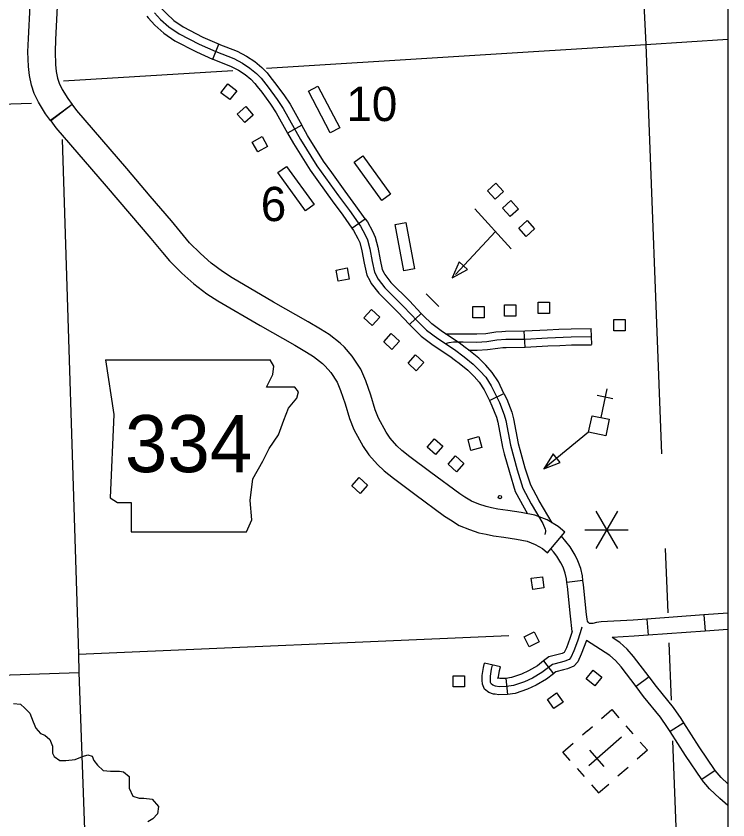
# Model space of a CAD drawing. Extents: x 155 to 3386, y 68 to 2138.
# Drawn here: x 2154 to 2342.2, y 715.4 to 927.8 of the extents above; entities that cross this region are included whole.
import ezdxf

# ---------------------------------------------------------------- set-up
doc = ezdxf.new("R2010")
doc.units = 0
for name, color, linetype in [('Default', 7, 'Continuous'), ('E_No Plot', 7, 'Continuous'), ('Level 10', 7, 'Continuous'), ('Level 21', 7, 'Continuous'), ('Level 31', 7, 'Continuous'), ('Level 32', 7, 'Continuous'), ('Level 35', 7, 'Continuous'), ('Level 4', 7, 'Continuous'), ('Level 48', 7, 'Continuous'), ('Level 5', 7, 'Continuous'), ('Level 56', 7, 'Continuous'), ('Level 57', 7, 'Continuous')]:
    doc.layers.add(name, color=color, linetype=linetype)

msp = doc.modelspace()

# ---------------------------------------------------------------- linework, layer by layer
at = {"layer": 'Default'}
msp.add_lwpolyline([(1150.5, 1308.99), (2342.15, 1308.99), (2342.15, 348.58), (1150.5, 348.58)], close=True, dxfattribs=at)
at = {"layer": 'E_No Plot'}
msp.add_lwpolyline([(1150.5, 1308.99), (2342.15, 1308.99), (2342.15, 348.58), (1150.5, 348.58)], close=True, dxfattribs=at)
msp.add_lwpolyline([(1150.5, 1308.99), (2342.15, 1308.99), (2342.15, 348.58), (1150.5, 348.58)], close=True, dxfattribs=at)
at = {"layer": 'Level 10'}
for p, q in [((2168.87, 904.47), (2163.16, 900.19)), ((2294.44, 786.01), (2299.05, 791.47))]:
    msp.add_line(p, q, dxfattribs=at)
for points in [[(2163.16, 900.19), (2161.77, 902.03), (2159.95, 905.04), (2158.8, 907.4), (2158.08, 909.54), (2157.58, 912.08), (2157.3, 914.48), (2157.17, 918.35), (2157.3, 921.92), (2157.78, 930.57)], [(2164.92, 930.33), (2164.43, 921.6), (2164.32, 918.34), (2164.43, 915.01), (2164.64, 913.18), (2164.99, 911.39), (2165.42, 910.12), (2166.23, 908.46), (2167.7, 906.04), (2168.87, 904.47)], [(2168.87, 904.47), (2163.19, 900.15), (2163.16, 900.19)], [(2299.05, 791.47), (2297.26, 792.98), (2294.35, 794.67), (2291.12, 795.96), (2287.48, 796.68), (2283.98, 797.18), (2281.36, 797.57), (2279.63, 797.88), (2278.24, 798.19), (2276.35, 798.83), (2274.38, 799.61), (2272.66, 800.71), (2271.3, 801.58), (2263.63, 807.24), (2258.11, 811.35), (2256, 813.03), (2254.69, 814.29), (2252.9, 816.29), (2251.85, 817.85), (2249.8, 821.57), (2248.95, 823.81), (2247.78, 827.61), (2246.47, 831.45), (2245.17, 834.48), (2242.88, 837.99), (2240.81, 840.36), (2239.64, 841.42), (2236.77, 843.71), (2234.52, 845.13), (2231.24, 847.06), (2222.07, 852.22), (2211.14, 858.62), (2208.55, 860.3), (2205.57, 862.57), (2202.75, 865.07), (2199.86, 867.94), (2198.29, 869.88), (2195.12, 873.7), (2189.47, 880.27), (2183.29, 887.55), (2170.12, 902.85), (2168.84, 904.51)], [(2163.19, 900.15), (2164.58, 898.33), (2177.86, 882.91), (2184.04, 875.63), (2189.66, 869.09), (2192.77, 865.35), (2194.55, 863.15), (2197.87, 859.86), (2201.02, 857.06), (2204.44, 854.46), (2207.39, 852.54), (2218.51, 846.02), (2227.68, 840.87), (2230.8, 839.03), (2232.63, 837.88), (2235, 835.98), (2235.72, 835.33), (2237.18, 833.67), (2238.85, 831.09), (2239.8, 828.88), (2240.99, 825.4), (2242.19, 821.5), (2243.3, 818.57), (2245.75, 814.12), (2247.26, 811.89), (2249.55, 809.33), (2251.29, 807.66), (2253.75, 805.69), (2259.38, 801.5), (2267.24, 795.7), (2268.8, 794.69), (2271.11, 793.23), (2273.89, 792.12), (2276.32, 791.3), (2278.22, 790.88), (2280.21, 790.52), (2282.95, 790.11), (2286.28, 789.64), (2289.09, 789.08), (2291.22, 788.23), (2293.13, 787.12), (2294.44, 786.01)]]:
    msp.add_lwpolyline(points, dxfattribs=at)
at = {"layer": 'Level 21'}
for p, q in [((2177.67, 837), (2179.85, 822.5)), ((2222.14, 835.3), (2221.14, 836.97)), ((2221.9, 833.13), (2222.14, 835.3)), ((2220.21, 829.75), (2221.9, 833.13)), ((2227.7, 829.75), (2220.21, 829.75)), ((2228.67, 828.54), (2227.7, 829.75)), ((2228.19, 826.85), (2228.67, 828.54)), ((2226.01, 824.19), (2228.19, 826.85)), ((2224.8, 821.04), (2226.01, 824.19)), ((2179.85, 822.5), (2178.88, 800.5)), ((2223.35, 817.18), (2224.8, 821.04)), ((2220.94, 813.55), (2223.35, 817.18)), ((2219.24, 810.17), (2220.94, 813.55)), ((2216.59, 805.58), (2219.24, 810.17)), ((2215.86, 799.78), (2216.59, 805.58)), ((2178.88, 800.5), (2180.82, 799.29)), ((2180.82, 799.29), (2184.44, 799.29)), ((2184.44, 799.29), (2184.44, 791.56)), ((2216.34, 794.7), (2215.86, 799.78)), ((2214.89, 791.56), (2216.34, 794.7)), ((2184.44, 791.56), (2214.89, 791.56))]:
    msp.add_line(p, q, dxfattribs=at)
msp.add_lwpolyline([(2177.67, 837), (2221.14, 836.97)], dxfattribs=at)
at = {"layer": 'Level 31'}
for p, q in [((2206.03, 916.43), (2207.59, 920.42)), ((2229.51, 899.01), (2225.77, 896.92)), ((2229.51, 899.01), (2229.51, 899.01)), ((2242.8, 871.77), (2246.29, 874.25)), ((2261.11, 849.24), (2257.99, 846.31)), ((2261.11, 849.24), (2261.11, 849.24)), ((2279.11, 826.25), (2282.96, 828.13))]:
    msp.add_line(p, q, dxfattribs=at)
for points in [[(2207.59, 920.42), (2212.42, 918.54), (2214.93, 917.26), (2217.1, 915.83), (2219, 914.26), (2220.4, 912.79), (2221.1, 911.9)], [(2206.81, 918.43), (2211.54, 916.58), (2213.85, 915.41), (2215.83, 914.1), (2217.54, 912.69), (2218.78, 911.39), (2220.65, 909.01), (2223.07, 905.75), (2224.61, 903.41), (2229.18, 895.22), (2233.53, 888.28), (2239.26, 880.3), (2242.11, 876.44), (2245.06, 872.29), (2246.29, 870.01), (2246.9, 868.7), (2247.5, 866.28), (2248.12, 862.93), (2248.79, 860.12), (2249.69, 858.34), (2251.5, 856.03), (2256.46, 851.07), (2260.11, 847.18), (2262.52, 844.85), (2265.5, 842.64), (2269.86, 839.72), (2272.41, 837.81), (2274.86, 835.82), (2276.63, 834.08), (2278.14, 832.37), (2279.61, 830.09), (2281.76, 825.7), (2283.03, 822.48), (2283.43, 820.96), (2284.67, 814.42), (2286.45, 807.89), (2287.96, 803.08), (2290.2, 798.93), (2293.22, 793.76), (2293.89, 792.26), (2293.93, 791.9), (2293.92, 791.63), (2293.79, 790.87)], [(2206.03, 916.43), (2210.66, 914.62), (2212.77, 913.55), (2214.55, 912.38), (2216.07, 911.12), (2217.15, 909.98), (2217.73, 909.25)], [(2221.1, 911.9), (2222.36, 910.31), (2224.82, 906.98), (2226.44, 904.52), (2229.51, 899.01)], [(2217.73, 909.25), (2218.95, 907.7), (2221.31, 904.53), (2222.77, 902.3), (2225.77, 896.92)], [(2237.46, 886.49), (2235.31, 889.48), (2231.02, 896.31), (2229.51, 899.01)], [(2225.77, 896.92), (2227.33, 894.13), (2231.75, 887.09), (2233.97, 883.99)], [(2246.29, 874.25), (2243.84, 877.7), (2240.99, 881.56), (2237.46, 886.49)], [(2233.97, 883.99), (2237.53, 879.04), (2240.37, 875.19), (2242.8, 871.77)], [(2246.29, 874.25), (2246.88, 873.42), (2248.21, 870.97), (2248.93, 869.41), (2249.6, 866.73), (2250.21, 863.37), (2250.81, 860.86), (2251.32, 859.86)], [(2242.8, 871.77), (2243.23, 871.15), (2244.38, 869.05), (2244.87, 867.99), (2245.4, 865.82), (2246.02, 862.49), (2246.76, 859.37), (2247.5, 857.92)], [(2251.32, 859.86), (2251.51, 859.5), (2253.11, 857.45), (2258, 852.56), (2261.11, 849.24)], [(2247.5, 857.92), (2247.88, 857.18), (2249.89, 854.6), (2254.92, 849.58), (2257.99, 846.31)], [(2272.72, 840.26), (2271.1, 841.47), (2266.74, 844.39), (2263.91, 846.49), (2261.64, 848.68), (2261.11, 849.24)], [(2257.99, 846.31), (2258.58, 845.67), (2261.13, 843.21), (2264.27, 840.89), (2268.62, 837.98), (2270.14, 836.83)], [(2282.96, 828.13), (2281.48, 831.15), (2279.85, 833.67), (2278.19, 835.56), (2276.29, 837.42), (2273.72, 839.5), (2272.72, 840.26)], [(2270.14, 836.83), (2271.09, 836.12), (2273.43, 834.22), (2275.08, 832.6), (2276.43, 831.07), (2277.75, 829.04), (2279.11, 826.25)], [(2282.96, 828.13), (2283.72, 826.57), (2285.07, 823.15), (2285.52, 821.43), (2286.76, 814.91), (2287.2, 813.31)], [(2279.11, 826.25), (2279.8, 824.83), (2280.99, 821.81), (2281.34, 820.49), (2282.58, 813.94), (2283.06, 812.18)], [(2283.06, 812.18), (2284.39, 807.29), (2285.97, 802.24), (2288.33, 797.88), (2289.23, 796.33)], [(2287.2, 813.31), (2288.51, 808.49), (2289.94, 803.92), (2292.07, 799.98), (2292.2, 799.76)], [(2292.2, 799.76), (2295.59, 793.95)]]:
    msp.add_lwpolyline(points, dxfattribs=at)
at = {"layer": 'Level 32'}
for p, q in [((2288.61, 840.32), (2288.3, 844.6)), ((2306.23, 841), (2306.04, 845.28)), ((2303.85, 778.71), (2299.6, 778.18)), ((2335.8, 769.57), (2336.11, 765.3)), ((2320.76, 768.49), (2321.07, 764.21)), ((2293.41, 757.42), (2296.05, 754.04)), ((2283.46, 752.82), (2283.86, 748.55)), ((2321.32, 753.22), (2317.91, 750.63)), ((2330.52, 741.07), (2326.91, 738.75)), ((2338.77, 728.5), (2335.22, 726.1))]:
    msp.add_line(p, q, dxfattribs=at)
for points in [[(2190.62, 928.7), (2192.23, 926.95), (2194.39, 924.98), (2197.12, 923.14), (2202.46, 920.36), (2206.81, 918.43)], [(2192.18, 930.22), (2192.31, 930.03), (2193.75, 928.47), (2195.72, 926.67), (2198.22, 924.98), (2203.39, 922.29), (2203.41, 922.28)], [(2188.63, 927.83), (2188.93, 927.37), (2190.72, 925.43), (2193.06, 923.29), (2196.03, 921.29), (2201.53, 918.43), (2201.67, 918.36)], [(2203.4, 922.28), (2207.68, 920.39)], [(2201.67, 918.36), (2205.94, 916.47)], [(2267.51, 843.88), (2272.2, 843.88), (2275.77, 843.82), (2278.17, 843.98), (2280.85, 844.37), (2282.38, 844.48)], [(2282.38, 844.48), (2283.35, 844.55), (2288.46, 844.61), (2294.36, 844.94), (2297.51, 845.08)], [(2297.51, 845.08), (2300.69, 845.22), (2306.04, 845.28)], [(2267.54, 841.28), (2268.48, 841.57), (2269.66, 841.74), (2272.18, 841.74), (2275.82, 841.68), (2278.4, 841.85), (2281.09, 842.24), (2283.44, 842.41), (2288.54, 842.46), (2294.47, 842.8), (2300.75, 843.08), (2306.07, 843.14)], [(2273.63, 839.57), (2275.87, 839.54), (2278.62, 839.72), (2281.32, 840.11), (2282.69, 840.21)], [(2282.69, 840.21), (2283.53, 840.27), (2288.61, 840.32), (2294.58, 840.66), (2297.7, 840.8)], [(2297.7, 840.8), (2300.8, 840.94), (2306.09, 840.99)], [(2303.85, 778.71), (2303.7, 779.91), (2303.25, 781.81), (2302.53, 783.86), (2301.74, 785.4), (2300.49, 787.59), (2299.34, 788.98), (2298.15, 790.4)], [(2299.6, 778.18), (2299.48, 779.15), (2299.13, 780.6), (2298.58, 782.16), (2297.97, 783.36), (2296.96, 785.14), (2296.04, 786.24), (2295.34, 787.08)], [(2300.97, 765.17), (2300.52, 769.21), (2299.73, 777.09), (2299.6, 778.18)], [(2305.83, 767.33), (2305.64, 767.32), (2305.55, 767.34), (2305.51, 767.36), (2305.21, 767.68), (2305.07, 767.92), (2304.92, 768.48), (2304.79, 769.66), (2303.99, 777.57), (2303.85, 778.71)], [(2335.8, 769.57), (2320.76, 768.49)], [(2342.15, 770.03), (2335.8, 769.57)], [(2320.76, 768.49), (2317.11, 768.23), (2308.68, 767.73), (2307.46, 767.56), (2306.43, 767.34), (2305.83, 767.33)], [(2303.56, 766.31), (2303.11, 764.83), (2302.42, 762.61), (2301.43, 760.07), (2300.64, 758.36), (2300.16, 757.84), (2299.07, 757.36), (2298.14, 757.12), (2295.78, 756.51), (2295.06, 755.99), (2293.01, 754.38), (2290.47, 752.91), (2288.38, 751.92), (2285.47, 750.96), (2283.66, 750.68), (2281.74, 750.61), (2280.71, 750.75), (2280.03, 750.99), (2279.58, 751.33), (2279.41, 751.74), (2279.38, 752.43), (2279.38, 753.39), (2279.69, 755.27), (2279.93, 756.34)], [(2300.97, 765.17), (2300.4, 763.31), (2299.46, 760.91), (2298.86, 759.61), (2298.37, 759.39), (2297.6, 759.2), (2294.86, 758.48), (2293.78, 757.71), (2293.41, 757.42)], [(2336.11, 765.3), (2321.07, 764.21)], [(2342.15, 765.74), (2336.11, 765.3)], [(2304.82, 762.84), (2303.4, 759.23), (2302.45, 757.15), (2301.43, 756.06), (2299.77, 755.33), (2298.68, 755.05), (2296.71, 754.53), (2296.35, 754.28), (2296.05, 754.04)], [(2317.91, 750.63), (2313.92, 755.9), (2312.48, 757.52), (2310.95, 758.87), (2304.82, 762.84)], [(2321.07, 764.21), (2317.38, 763.95), (2311.53, 763.61)], [(2321.32, 753.22), (2317.23, 758.62), (2315.52, 760.56), (2313.55, 762.3), (2311.53, 763.61)], [(2280.63, 748.6), (2280.21, 748.66), (2279, 749.08), (2277.83, 749.98), (2277.29, 751.27), (2277.24, 752.38), (2277.24, 753.56), (2277.58, 755.68), (2277.84, 756.81)], [(2281.52, 752.81), (2281.52, 753.22), (2281.79, 754.86), (2282.02, 755.86), (2277.84, 756.81)], [(2293.41, 757.42), (2291.8, 756.16), (2289.47, 754.81), (2287.59, 753.91), (2284.98, 753.05), (2283.46, 752.82), (2281.85, 752.76), (2281.19, 752.85)], [(2296.05, 754.04), (2294.21, 752.6), (2291.47, 751.01), (2289.18, 749.92), (2285.97, 748.86), (2283.86, 748.55), (2281.64, 748.47), (2280.63, 748.6)], [(2330.52, 741.07), (2329.79, 742.21), (2327.73, 745.16), (2323.25, 750.67), (2321.32, 753.22)], [(2326.91, 738.75), (2326.22, 739.83), (2324.31, 742.57), (2319.88, 748.02), (2317.91, 750.63)], [(2338.77, 728.5), (2334.56, 734.76), (2330.52, 741.07)], [(2335.22, 726.1), (2330.97, 732.41), (2326.91, 738.75)], [(2342.15, 724.98), (2340.37, 726.64), (2338.79, 728.48), (2338.77, 728.5)], [(2342.15, 719.18), (2340.01, 721.11), (2337.28, 723.67), (2335.37, 725.88), (2335.22, 726.11)]]:
    msp.add_lwpolyline(points, dxfattribs=at)
at = {"layer": 'Level 35'}
msp.add_lwpolyline([(2153.37, 746.16), (2155.23, 746.01), (2156.34, 744.97), (2157.67, 743.63), (2158.56, 741.33), (2159.23, 739.7), (2160.49, 738.22), (2161.6, 737.85), (2162.94, 736.66), (2163.68, 734.88), (2163.68, 733.02), (2164.13, 732.13), (2165.61, 731.1), (2167.17, 731.1), (2169.61, 731.39), (2171.61, 732.21), (2173.02, 732.58), (2174.14, 732.28), (2174.58, 731.1), (2175.54, 729.91), (2177.03, 728.43), (2178.96, 728.28), (2181.4, 728.28), (2182.44, 728.13), (2183.92, 726.87), (2183.92, 725.16), (2183.92, 723.83), (2184.89, 721.67), (2186.59, 721.16), (2187.78, 721.16), (2190, 720.93), (2191.64, 718.93), (2191.41, 717), (2190.15, 715.74), (2188.89, 714.92)], dxfattribs=at)
at = {"layer": 'Level 4'}
msp.add_lwpolyline([(2166.22, 895.2), (2170.5, 759.17), (2170.66, 754.35), (2175.91, 607.74), (2176.09, 602.62), (2177.54, 562.78)], dxfattribs=at)
at = {"layer": 'Level 48'}
for p, q in [((2312.94, 797.02), (2307.22, 787.12)), ((2307.22, 797.02), (2312.94, 787.12)), ((2304.36, 792.07), (2315.79, 792.07))]:
    msp.add_line(p, q, dxfattribs=at)
at = {"layer": 'Level 5'}
for points in [[(2312.91, 1072.42), (2320.42, 920.32)], [(2220.25, 914.04), (2320.42, 920.32)], [(2320.42, 920.32), (2342.15, 921.7)], [(2320.42, 920.32), (2324.61, 812.11)], [(2166.57, 910.68), (2211.33, 913.48)], [(2049.37, 901.35), (2050.87, 901.38), (2158.1, 904.79)], [(2325.58, 787.12), (2326.24, 770.14)], [(2170.5, 759.17), (2284.25, 764.17)], [(2326.54, 762.25), (2327.12, 747.06)], [(2077.31, 751.18), (2170.66, 754.35)], [(2327.53, 736.31), (2330.9, 647.63)]]:
    msp.add_lwpolyline(points, dxfattribs=at)
at = {"layer": 'Level 56'}
for points in [[(2210.5, 905.74), (2208.17, 907.58), (2210.01, 909.93), (2212.35, 908.09)], [(2239.59, 898.26), (2237.06, 896.94), (2231.27, 908.02), (2233.81, 909.34)], [(2212.5, 901.93), (2214.74, 903.89), (2216.7, 901.64), (2214.46, 899.68)], [(2220.51, 893.4), (2217.92, 891.95), (2216.46, 894.55), (2219.06, 896)], [(2253.02, 880.76), (2250.7, 879.09), (2243.37, 889.21), (2245.68, 890.89)], [(2232.82, 878), (2230.5, 876.32), (2223.17, 886.45), (2225.48, 888.12)], [(2282.81, 881.48), (2280.61, 879.48), (2278.6, 881.69), (2280.8, 883.69)], [(2286.81, 876.84), (2284.61, 874.85), (2282.61, 877.05), (2284.81, 879.05)], [(2254.21, 872.78), (2257.02, 873.3), (2259.29, 861.01), (2256.48, 860.49)], [(2291.07, 871.58), (2288.87, 869.59), (2286.86, 871.8), (2289.07, 873.79)], [(2273.3, 860.87), (2271.17, 862.85), (2269.26, 858.66)], [(2238.59, 860.72), (2241.52, 861.26), (2242.06, 858.33), (2239.13, 857.79)], [(2291.97, 849.24), (2291.97, 852.22), (2294.96, 852.22), (2294.96, 849.24)], [(2250.17, 848.27), (2248.14, 846.1), (2245.96, 848.13), (2247.98, 850.3)], [(2274.73, 848.11), (2274.73, 851.08), (2277.71, 851.08), (2277.71, 848.11)], [(2283.13, 848.57), (2283.13, 851.54), (2286.11, 851.54), (2286.11, 848.57)], [(2311.97, 844.65), (2311.97, 847.62), (2314.96, 847.62), (2314.96, 844.65)], [(2255.39, 841.9), (2253.36, 839.72), (2251.18, 841.75), (2253.2, 843.93)], [(2261.82, 836.27), (2259.79, 834.1), (2257.61, 836.13), (2259.63, 838.3)], [(2266.84, 814.19), (2264.89, 811.94), (2262.64, 813.9), (2264.59, 816.14)], [(2273.48, 815.95), (2276.36, 816.7), (2277.11, 813.81), (2274.23, 813.07)], [(2272.4, 809.62), (2270.4, 807.42), (2268.2, 809.43), (2270.2, 811.63)], [(2246.94, 803.85), (2244.94, 801.66), (2242.73, 803.67), (2244.74, 805.86)], [(2290.58, 776.34), (2290.19, 779.29), (2293.14, 779.68), (2293.54, 776.73)], [(2289.62, 761.12), (2288.3, 763.78), (2290.97, 765.11), (2292.3, 762.44)], [(2304.65, 752.71), (2306.54, 755.01), (2308.84, 753.11), (2306.95, 750.81)], [(2269.53, 750.56), (2269.53, 753.53), (2272.52, 753.53), (2272.52, 750.56)], [(2296.17, 744.83), (2294.43, 747.24), (2296.86, 748.98), (2298.59, 746.57)]]:
    msp.add_lwpolyline(points, close=True, dxfattribs=at)
for points in [[(2284.91, 866.3), (2275.3, 876.89)], [(2270.14, 859.54), (2280.71, 870.93)], [(2265.75, 851.05), (2262.37, 854.43)]]:
    msp.add_lwpolyline(points, dxfattribs=at)
at = {"layer": 'Level 57'}
for p, q in [((2310.11, 829.29), (2308.54, 821.76)), ((2307.57, 827.63), (2311.77, 826.75)), ((2305.02, 738.94), (2306.38, 740.13)), ((2317.1, 738.14), (2315.22, 740.3)), ((2305.02, 738.94), (2303.69, 737.78)), ((2305.42, 729.8), (2314.02, 737.33)), ((2309.45, 729.53), (2305.67, 733.85)), ((2309.72, 733.57), (2309.72, 733.57)), ((2309.72, 733.57), (2309.72, 733.57)), ((2302.32, 729.01), (2304.2, 726.86)), ((2313.1, 727.03), (2315.78, 729.38))]:
    msp.add_line(p, q, dxfattribs=at)
for points in [[(2305.35, 817.87), (2306.27, 822.23), (2310.79, 821.28), (2309.88, 816.92)], [(2297.85, 809.86), (2296, 812.12), (2293.54, 808.22)]]:
    msp.add_lwpolyline(points, close=True, dxfattribs=at)
for points in [[(2305.35, 817.87), (2293.54, 808.22)], [(2308.78, 742.23), (2311.47, 744.58), (2313.35, 742.43)], [(2300.44, 731.15), (2298.56, 733.3), (2301.25, 735.65)], [(2318.99, 735.98), (2320.87, 733.83), (2318.18, 731.48)], [(2306.09, 724.7), (2307.97, 722.55), (2310.66, 724.9)]]:
    msp.add_lwpolyline(points, dxfattribs=at)
msp.add_circle((2281.9, 800.71), 0.429, dxfattribs=at)

# ---------------------------------------------------------------- texts
at = {"layer": 'Level 21'}
msp.add_text('334', height=15.086, dxfattribs=at).set_placement((2182.8, 807.3))
at = {"layer": 'Level 56'}
for s, height, p in [('10', 9.051, (2241.32, 900.08)), ('6', 9.05, (2218.7, 873.65))]:
    msp.add_text(s, height=height, dxfattribs=at).set_placement(p)

doc.saveas('drawing.dxf')
